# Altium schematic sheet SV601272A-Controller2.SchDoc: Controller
size 431 x 279 mm; Date: Not shown in title block; ApprovedBy: Not shown in title block; CheckedBy: Not shown in title block; Author: Not shown in title block; CompanyName: Not shown in title block; Engineer: Not shown in title block; Organization: Not shown in title block; Address1: Not shown in title block; Address2: Not shown in title block; Address3: Not shown in title block; Address4: Not shown in title block; DocumentNumber: 4; Revision: Use project parameter SCH_Rev; SheetNumber: 4; SheetTotal: 11; PageSetup: Record=PageOptions¦CenterHorizontal=True¦CenterVertical=True¦PrintScale=1.00¦XCorrection=1.00¦YCorrection=1.00¦PrintKind=0¦BorderSize=5000000¦LeftOffset=0¦BottomOffset=0¦Orientation=2¦PaperLength=1000¦PaperWidth=1000¦Scale=100¦PaperSource=15¦PrintQuality=600¦MediaType=1¦DitherType=10¦PaperKind=Letter¦PrintScaleMode=1
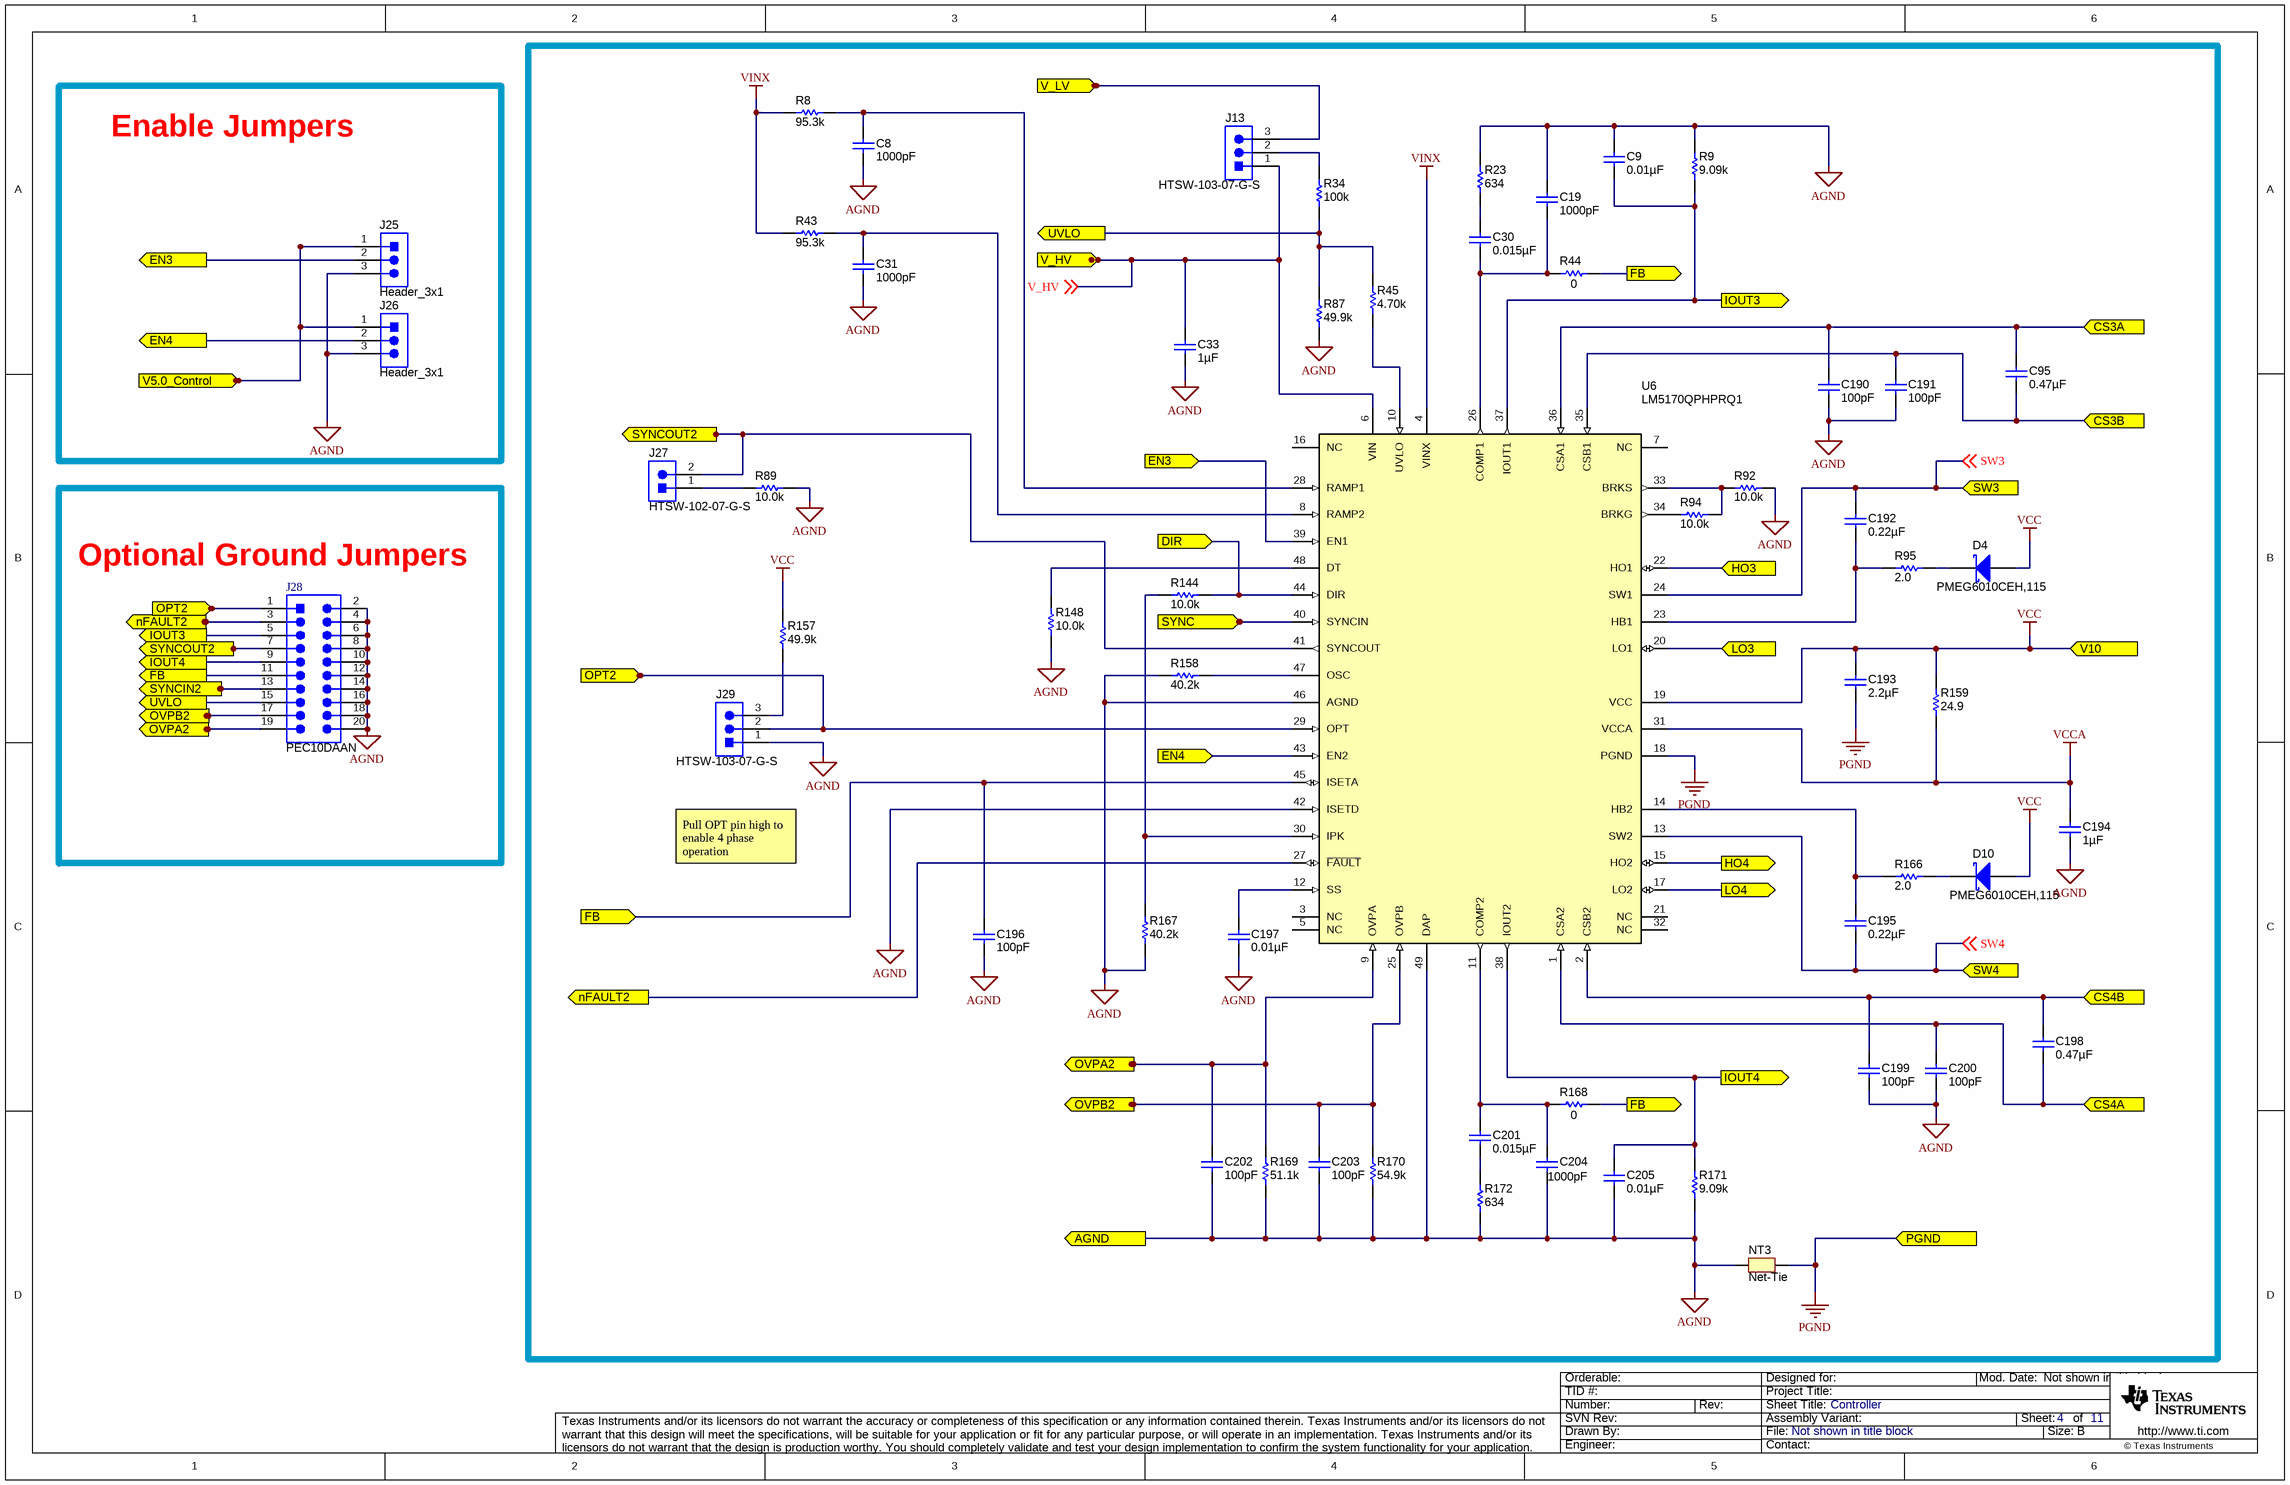
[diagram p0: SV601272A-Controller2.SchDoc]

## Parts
C8  ValueDisplayed: 1000pF  [0603L]  (hidden comment: C1608C0G2A102J080AA)
C9  ValueDisplayed: 0.01µF  [0603L]  (hidden comment: 06031C103KAT2A)
C19  ValueDisplayed: 1000pF  [0603L]  (hidden comment: C1608C0G2A102J080AA)
C30  ValueDisplayed: 0.015µF  [0603L]  (hidden comment: GRM188R71E153KA01D)
C31  ValueDisplayed: 1000pF  [0603L]  (hidden comment: C1608C0G2A102J080AA)
C33  ValueDisplayed: 1µF  [0805_HV]  (hidden comment: C2012X7S2A105K125AB)
C95  ValueDisplayed: 0.47µF  [0603L]  (hidden comment: GRM188R71C474KA88D)
C190  ValueDisplayed: 100pF  [0603L]  (hidden comment: C0603C101J5GACTU)
C191  ValueDisplayed: 100pF  [0603L]  (hidden comment: C0603C101J5GACTU)
C192  ValueDisplayed: 0.22µF  [0603L]  (hidden comment: C1608X7R1H224K080AB)
C193  ValueDisplayed: 2.2µF  [0805_HV]  (hidden comment: C2012X7R1C225K125AB)
C194  ValueDisplayed: 1µF  [0603L]  (hidden comment: GRM188R71E105KA12D)
C195  ValueDisplayed: 0.22µF  [0603L]  (hidden comment: C1608X7R1H224K080AB)
C196  ValueDisplayed: 100pF  [0603L]  (hidden comment: C0603C101J5GACTU)
C197  ValueDisplayed: 0.01µF  [0603L]  (hidden comment: 06031C103KAT2A)
C198  ValueDisplayed: 0.47µF  [0603L]  (hidden comment: GRM188R71C474KA88D)
C199  ValueDisplayed: 100pF  [0603L]  (hidden comment: C0603C101J5GACTU)
C200  ValueDisplayed: 100pF  [0603L]  (hidden comment: C0603C101J5GACTU)
C201  ValueDisplayed: 0.015µF  [0603L]  (hidden comment: GRM188R71E153KA01D)
C202  ValueDisplayed: 100pF  [0603L]  (hidden comment: C0603C101J5GACTU)
C203  ValueDisplayed: 100pF  [0603L]  (hidden comment: C0603C101J5GACTU)
C204  ValueDisplayed: 1000pF  [0603L]  (hidden comment: C1608C0G2A102J080AA)
C205  ValueDisplayed: 0.01µF  [0603L]  (hidden comment: 06031C103KAT2A)
D4  PMEG6010CEH,115  [SOD-123F]
D10  PMEG6010CEH,115  [SOD-123F]
J13  HTSW-103-07-G-S  [Samtec_HTSW-103-07-G-S]
J25  Header_3x1  [Samtec_HTSW-103-07-G-S]
J26  Header_3x1  [Samtec_HTSW-103-07-G-S]
J27  HTSW-102-07-G-S  [Samtec_HTSW-102-07-G-S]
J28  PEC10DAAN  [SULLINS_PEC10DAAN]
J29  HTSW-103-07-G-S  [Samtec_HTSW-103-07-G-S]
NT3  Net-Tie  [Net-Tie_10mil]  (net tie, no BOM)
R8  ValueDisplayed: 95.3k  [0603L]  (hidden comment: CRCW060395K3FKEA)
R9  ValueDisplayed: 9.09k  [0603L]  (hidden comment: CRCW06039K09FKEA)
R23  ValueDisplayed: 634  [0603L]  (hidden comment: CRCW0603634RFKEA)
R34  ValueDisplayed: 100k  [0603]  (hidden comment: CRCW0603100KFKEA)
R43  ValueDisplayed: 95.3k  [0603L]  (hidden comment: CRCW060395K3FKEA)
R44  ValueDisplayed: 0  [0603]  (hidden comment: Resistor)
R45  ValueDisplayed: 4.70k  [0603]  (hidden comment: RC0603FR-074K7L)
R87  ValueDisplayed: 49.9k  [0603]  (hidden comment: ERJ-3EKF4992V)
R89  ValueDisplayed: 10.0k  [0603L]  (hidden comment: CRCW060310K0FKEA)
R92  ValueDisplayed: 10.0k  [0603]  (hidden comment: ERJ-3EKF1002V)
R94  ValueDisplayed: 10.0k  [0603]  (hidden comment: ERJ-3EKF1002V)
R95  ValueDisplayed: 2.0  [0805_HV]  (hidden comment: CRCW08052R00JNEA)
R144  ValueDisplayed: 10.0k  [0603L]  (hidden comment: CRCW060310K0FKEA)
R148  ValueDisplayed: 10.0k  [0603L]  (hidden comment: CRCW060310K0FKEA)
R157  ValueDisplayed: 49.9k  [0603L]  (hidden comment: CRCW060349K9FKEA)
R158  ValueDisplayed: 40.2k  [0603L]  (hidden comment: CRCW060340K2FKEA)
R159  ValueDisplayed: 24.9  [0805L]  (hidden comment: CRCW080524R9FKEA)
R166  ValueDisplayed: 2.0  [0805_HV]  (hidden comment: CRCW08052R00JNEA)
R167  ValueDisplayed: 40.2k  [0603]  (hidden comment: ERJ-3EKF4022V)
R168  ValueDisplayed: 0  [0603]  (hidden comment: Resistor)
R169  ValueDisplayed: 51.1k  [0603L]  (hidden comment: CRCW060351K1FKEA)
R170  ValueDisplayed: 54.9k  [0603L]  (hidden comment: CRCW060354K9FKEA)
R171  ValueDisplayed: 9.09k  [0603L]  (hidden comment: CRCW06039K09FKEA)
R172  ValueDisplayed: 634  [0603L]  (hidden comment: CRCW0603634RFKEA)
U6  LM5170QPHPRQ1  [PHP0048D_L]

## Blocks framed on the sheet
Enable Jumpers: J25 J26
Optional Ground Jumpers: J28

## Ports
AGND, CS3A, CS3B, CS4A, CS4B, DIR, EN3, EN4, FB, HO3, HO4, IOUT3, IOUT4, LO3, LO4, nFAULT2, OPT2, OVPA2, OVPB2, PGND, SW3, SW4, SYNC, SYNCIN2, SYNCOUT2, UVLO, V5.0_Control, V10, V_HV, V_LV

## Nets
AGND: C8.2 C9.1 C19.1 C31.2 C33.2 C190.2 C191.2 C194.2 C196.2 C197.2 C199.2 C200.2 C202.2 C203.2 C204.2 C205.2 J25.3 J26.3 J28.2 J28.4 J28.6 J28.8 J28.10 J28.12 J28.14 J28.16 J28.18 J28.20 J29.1 NT3.1 R9.2 R23.2 R87.1 R89.2 R92.1 R148.1 R158.1 R167.1 R169.1 R170.1 R171.1 R172.1 U6.42(ISETD) U6.46(AGND) U6.49(DAP) ; port AGND
PGND: C193.2 NT3.2 U6.18(PGND) ; port PGND
VCC: C193.1 D4.2(A) D10.2(A) R157.2 R159.2 U6.19(VCC) ; port V10
VCCA: C194.1 R159.1 U6.31(VCCA)
VINX: R8.1 R43.1 U6.4(VINX)
CS3A: C95.1 C190.1 U6.36(CSA1) ; port CS3A
CS3B: C95.2 C191.1 U6.35(CSB1) ; port CS3B
CS4A: C198.2 C200.1 U6.1(CSA2) ; port CS4A
CS4B: C198.1 C199.1 U6.2(CSB2) ; port CS4B
DIR: R144.2 U6.44(DIR) ; port DIR
EN3: J25.2 U6.39(EN1) ; port EN3
EN4: J26.2 U6.43(EN2) ; port EN4
FB: C196.1 J28.11 R44.2 R168.2 U6.45(ISETA) ; port FB
HO3: U6.22(HO1) ; port HO3
HO4: U6.15(HO2) ; port HO4
IOUT3: C9.2 J28.5 R9.1 U6.37(IOUT1) ; port IOUT3
IOUT4: C205.1 J28.9 R171.2 U6.38(IOUT2) ; port IOUT4
LO3: U6.20(LO1) ; port LO3
LO4: U6.17(LO2) ; port LO4
nFAULT2: J28.3 U6.27(~{FAULT}) ; port nFAULT2
OPT2: J28.1 J29.2 U6.29(OPT) ; port OPT2
OVPA2: C202.1 J28.19 R169.2 U6.9(OVPA) ; port OVPA2
OVPB2: C203.1 J28.17 R170.2 U6.25(OVPB) ; port OVPB2
SW3: C192.1 U6.24(SW1) ; off-sheet SW3, port SW3
SW4: C195.2 U6.13(SW2) ; off-sheet SW4, port SW4
SYNC: U6.40(SYNCIN) ; port SYNC
SYNCIN2: J28.13 ; port SYNCIN2
SYNCOUT2: J27.2 J28.7 U6.41(SYNCOUT) ; port SYNCOUT2
UVLO: J28.15 R34.1 R45.2 R87.2 ; port UVLO
V5.0_Control: J25.1 J26.1 ; port V5.0_Control
V_HV: C33.1 J13.1 U6.6(VIN) ; off-sheet V_HV, port V_HV
V_LV: J13.3 ; port V_LV
NetC8_1: C8.1 R8.2 U6.28(RAMP1)
NetC19_2: C19.2 C30.2 R44.1 U6.26(COMP1)
NetC30_1: C30.1 R23.1
NetC31_1: C31.1 R43.2 U6.8(RAMP2)
NetC192_2: C192.2 R95.1 U6.23(HB1)
NetC195_1: C195.1 R166.1 U6.14(HB2)
NetC197_1: C197.1 U6.12(SS)
NetC201_1: C201.1 C204.1 R168.1 U6.11(COMP2)
NetC201_2: C201.2 R172.2
NetD4_1: D4.1(K) R95.2
NetD10_1: D10.1(K) R166.2
NetJ13_2: J13.2 R34.2
NetJ27_1: J27.1 R89.1
NetJ29_3: J29.3 R157.1
NetR45_1: R45.1 U6.10(UVLO)
NetR92_2: R92.2 R94.1 U6.33(BRKS)
NetR94_2: R94.2 U6.34(BRKG)
NetR144_1: R144.1 R167.2 U6.30(IPK)
NetR148_2: R148.2 U6.48(DT)
NetR158_2: R158.2 U6.47(OSC)

Not connected (* = marked no-connect by the designer): U6 3(NC) 5(NC) 7(NC) 16(NC) 21(NC) 32(NC)

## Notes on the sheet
- Pull OPT pin high to enable 4 phase operation

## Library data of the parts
C8 C19 C31 C204 = C1608C0G2A102J080AA: CAP, CERM, 1000 pF, 100 V, +/- 5%, C0G/NP0, 0603; Manufacturer: TDK; Polarized: N; CompType: Capacitor; Value: 1000pF; U/M: EA; Cap_F: 0.000000001; Tolerance_%: 5; ESR_ohm: 0.0589; Value1: 0.0589 ohm; VDC_V: 100; Value2: 100V; TaMin_C: -55; TaMax_C: 125; Cap_Case: 0603; AEC Category: Q200
C9 C197 C205 = 06031C103KAT2A: CAP, CERM, 0.01 µF, 100 V, +/- 10%, X7R, 0603; Manufacturer: AVX; Polarized: N; CompType: Capacitor; Value: 0.01uF; U/M: EA; Cap_F: 0.00000001; Tolerance_%: 10; ESR_ohm: 0.098; Value1: 0.098 ohm; VDC_V: 100; Value2: 100V; TaMin_C: -55; TaMax_C: 125; Cap_Case: 0603
C30 C201 = GRM188R71E153KA01D: CAP, CERM, 0.015 µF, 25 V, +/- 10%, X7R, 0603; Manufacturer: MuRata; Polarized: N; CompType: Capacitor; Value: 0.015uF; U/M: EA; Cap_F: 0.000000015; Tolerance_%: 10; Value1: Unknown; VDC_V: 25; Value2: 25V; TaMin_C: -55; TaMax_C: 125; Cap_Case: 0603
C33 = C2012X7S2A105K125AB: CAP, CERM, 1 µF, 100 V, +/- 10%, X7S, 0805; Manufacturer: TDK; Polarized: N; CompType: Capacitor; Value: 1uF; U/M: EA; Cap_F: 0.000001; Tolerance_%: 10; Value1: Unknown; VDC_V: 100; Value2: 100V; TaMin_C: -55; TaMax_C: 125; Cap_Case: 0805; AEC Category: Q200
C95 C198 = GRM188R71C474KA88D: CAP, CERM, 0.47 µF, 16 V, +/- 10%, X7R, 0603; Manufacturer: MuRata; Polarized: N; CompType: Capacitor; Value: 0.47uF; U/M: EA; Cap_F: 0.00000047; Tolerance_%: 10; Value1: Unknown; VDC_V: 16; Value2: 16V; TaMin_C: -55; TaMax_C: 125; Cap_Case: 0603; AEC Category: Q200
C190 C191 C199 C200 C202 C203 = C0603C101J5GACTU: CAP, CERM, 100 pF, 50 V, +/- 5%, C0G/NP0, 0603; Manufacturer: Kemet; Polarized: N; CompType: Capacitor; Value: 100pF; U/M: EA; Cap_F: 0.0000000001; Tolerance_%: 5; Value1: Unknown; VDC_V: 50; Value2: 50V; TaMin_C: -55; TaMax_C: 125; Cap_Case: 0603; AEC Category: Q200
C192 C195 = C1608X7R1H224K080AB: CAP, CERM, 0.22 µF, 50 V, +/- 10%, X7R, 0603; Manufacturer: TDK; Polarized: N; CompType: Capacitor; Value: 0.22uF; U/M: EA; Cap_F: 0.00000022; Tolerance_%: 10; Value1: Unknown; VDC_V: 50; Value2: 50V; TaMin_C: -55; TaMax_C: 125; Cap_Case: 0603
C193 = C2012X7R1C225K125AB: CAP, CERM, 2.2 µF, 16 V, +/- 10%, X7R, 0805; Manufacturer: TDK; CompType: Capacitor; Value: 2.2uF; U/M: EA; Tolerance_%: 10; VDC_V: 16; Polarized: N; Cap_F: 0.0000022; ESR_ohm: 0.0049; Value1: 0.0049 ohm; Value2: 16V; TaMin_C: -55; TaMax_C: 125; Cap_Case: 0805; AEC Category: Q200
C194 = GRM188R71E105KA12D: CAP, CERM, 1 µF, 25 V, +/- 10%, X7R, 0603; Manufacturer: MuRata; Polarized: N; CompType: Capacitor; Value: 1uF; U/M: EA; Cap_F: 0.000001; Tolerance_%: 10; Value1: Unknown; VDC_V: 25; Value2: 25V; TaMin_C: -55; TaMax_C: 125; Cap_Case: 0603
C196 = C0603C101J5GACTU: CAP, CERM, 100 pF, 50 V, +/- 5%, C0G/NP0, 0603; Manufacturer: Kemet; Polarized: N; CompType: Capacitor; Value: 100pF; U/M: EA; Cap_F: 0.0000000001; Tolerance_%: 5; Value1: Unknown; VDC_V: 50; Value2: 50V; TaMin_C: -55; TaMax_C: 125; Cap_Case: 0603; AEC Category: Q200; SizeArea_mm2: 1.28; SizeAreaWB_mm2: 4.68; SizeX_mm: 1.6; SizeY_mm: 0.8; SizeZ_mm: 1
D4 D10 = PMEG6010CEH,115: Diode, Schottky, 60 V, 1 A, SOD-123F; Manufacturer: NXP Semiconductor; U/M: EA; Vf_V: 0.57; Value: 60V; Value1: 1A; Value2: 0.57V; Io_A: 1; Vr_V: 60; TJmax_C: 150
J13 J29 = HTSW-103-07-G-S: Header, 100mil, 3x1, Gold, TH; Manufacturer: Samtec; SymbolCreator: a0799628; U/M: EA
J25 J26 = CMP-0075484-1: Header, 100mil, 3x1, Gold, TH; PartNumber: HTSW-103-07-G-S; Manufacturer: Samtec; CNHeader: True; CT: False; Green_Lifecycle: Active; Green_REACh: Passed
J27 = HTSW-102-07-G-S: Header, 100mil, 2x1, Gold, TH; Manufacturer: Samtec; SymbolCreator: a0412235; U/M: EA
J28 = CMP-0054623-2: Header, 2.54mm, 10x2, Tin, TH; Manufacturer: Sullins Connector Solutions; Current_A: 3A; Green_Lifecycle: Not Set; Shrouded: N; Gender: Male; Green_REACh: Incomplete; Row_Count: 2; RowSpacing_mm: 2.54; Cert_UL: Y
NT3 = Net-Tie: Single point connection between nets.; SymbolCreator: codlsc
R8 R43 = CRCW060395K3FKEA: RES, 95.3 k, 1%, 0.1 W, 0603; Manufacturer: Vishay-Dale; CompType: Resistor; Value: 95.3k; Res_ohm: 95300; Value_Code: 95k3; Tolerance_%: 1; Power_W: 0.1; Value2: 0.1W; VDC_V: 75; TempCo: 100 ppm/C; EIA_Code: E96; U/M: EA
R9 R171 = CRCW06039K09FKEA: RES, 9.09 k, 1%, 0.1 W, 0603; Manufacturer: Vishay-Dale; CompType: Resistor; Value: 9.09k; Res_ohm: 9090; Value_Code: 9k09; Tolerance_%: 1; Power_W: 0.1; Value2: 0.1W; VDC_V: 75; TempCo: 100 ppm/C; EIA_Code: E96; U/M: EA
R23 R172 = CRCW0603634RFKEA: RES, 634, 1%, 0.1 W, 0603; Manufacturer: Vishay-Dale; CompType: Resistor; Value: 634; Value_Code: 634R; Tolerance_%: 1; Power_W: 0.1; Value2: 0.1W; VDC_V: 75; TempCo: 100 ppm/C; EIA_Code: E96; U/M: EA
R34 = CMP-0021990-4: RES, 100 k, 1%, 0.1 W, AEC-Q200 Grade 0, 0603; Manufacturer: Vishay-Dale; Power_W: 100mW; TempCo: 100 ppm/C; Value: 100k; EIA_Code: E96; SizeX_mm: 1.6; SizeY_mm: 0.8; SizeZ_mm: 1; Value2: 0.1W; SizeArea_mm2: 1.28; CompType: Resistor; AEC Qualified: Y; VDC_V: 75V; AEC Category: Q200; AEC Grade: 0
R44 R168 = CMP-0025874-3: RES, 0, 5%, 0.1 W, 0603; PartNumber: ERJ-3GEY0R00V; Manufacturer: Panasonic; Value: 0; Value_Code: 0000; Power_W: 100mW; Value2: 0.1W; VDC_V: 50V; TempCo: 600 ppm/C; EIA_Code: E24; U/M: EA; AEC Category: Q200; SizeArea_mm2: 1.28; SizeX_mm: 1.6; SizeY_mm: 0.8; SizeZ_mm: 1
R45 = CMP-0023153-3: RES, 4.70 k, 1%, 0.1 W, 0603; Manufacturer: Yageo America; Power_W: 100mW; TempCo: 200 ppm/C; Value_Code: 4k70; U/M: EA; Value: 4.70k; Res_ohm: 4.7k; SizeX_mm: 1.6; SizeY_mm: 0.8; SizeZ_mm: 1; Value2: 0.1W; SizeArea_mm2: 1.28; CompType: Resistor; VDC_V: 150V; AEC Category: Q200
R87 = CMP-0022705-3: RES, 49.9 k, 1%, 0.1 W, AEC-Q200 Grade 0, 0603; Manufacturer: Panasonic; Power_W: 100mW; TempCo: 100 ppm/C; Value_Code: 49k9; U/M: EA; Value: 49.9k; EIA_Code: E96; SizeX_mm: 1.6; SizeY_mm: 0.8; SizeZ_mm: 1; Value2: 0.1W; SizeArea_mm2: 1.28; CompType: Resistor; AEC Qualified: Y; VDC_V: 75V; AEC Grade: 0; AEC Category: Q200
R89 R144 = CRCW060310K0FKEA: RES, 10.0 k, 1%, 0.1 W, 0603; Manufacturer: Vishay-Dale; CompType: Resistor; Value: 10.0k; Res_ohm: 10000; Value_Code: 10k0; Tolerance_%: 1; Power_W: 0.1; Value2: 0.1W; VDC_V: 75; TempCo: 100 ppm/C; EIA_Code: E96; U/M: EA
R92 R94 = CMP-0022684-3: RES, 10.0 k, 1%, 0.1 W, 0603; Manufacturer: Panasonic; Power_W: 100mW; TempCo: 100 ppm/C; Value_Code: 10k0; U/M: EA; Value: 10.0k; EIA_Code: E96; Res_ohm: 10k; SizeX_mm: 1.6; SizeY_mm: 0.8; SizeZ_mm: 1; Value2: 0.1W; SizeArea_mm2: 1.28; CompType: Resistor; VDC_V: 75V; AEC Category: Q200
R95 R166 = CRCW08052R00JNEA: RES, 2.0, 5%, 0.125 W, 0805; Manufacturer: Vishay-Dale; CompType: Resistor; Value: 2.0; Res_ohm: 2; Value_Code: 2R00; Tolerance_%: 5; Power_W: 0.125; Value2: 0.125W; VDC_V: 150; TempCo: 200 ppm/C; EIA_Code: E24; U/M: EA; AEC Category: Q200
R148 = CRCW060310K0FKEA: RES, 10.0 k, 1%, 0.1 W, 0603; Manufacturer: Vishay-Dale; CompType: Resistor; Value: 10.0k; Res_ohm: 10000; Value_Code: 10k0; Tolerance_%: 1; Power_W: 0.1; Value2: 0.1W; VDC_V: 75; TempCo: 100 ppm/C; EIA_Code: E96; U/M: EA; SizeArea_mm2: 1.28; SizeX_mm: 1.6; SizeY_mm: 0.8; AEC Category: Q200
R157 = CRCW060349K9FKEA: RES, 49.9 k, 1%, 0.1 W, 0603; Manufacturer: Vishay-Dale; CompType: Resistor; Value: 49.9k; Res_ohm: 49900; Value_Code: 49k9; Tolerance_%: 1; Power_W: 0.1; Value2: 0.1W; VDC_V: 75; TempCo: 100 ppm/C; EIA_Code: E96; U/M: EA
R158 = CRCW060340K2FKEA: RES, 40.2 k, 1%, 0.1 W, 0603; Manufacturer: Vishay-Dale; CompType: Resistor; Value: 40.2k; Res_ohm: 40200; Value_Code: 40k2; Tolerance_%: 1; Power_W: 0.1; Value2: 0.1W; VDC_V: 75; TempCo: 100 ppm/C; EIA_Code: E96; U/M: EA; SizeArea_mm2: 1.28; SizeX_mm: 1.6; SizeY_mm: 0.8; AEC Category: Q200
R159 = CRCW080524R9FKEA: RES, 24.9, 1%, 0.125 W, 0805; Manufacturer: Vishay-Dale; CompType: Resistor; Value: 24.9; Value_Code: 24R9; Tolerance_%: 1; Power_W: 0.125; Value2: 0.125W; VDC_V: 150; TempCo: 100 ppm/C; EIA_Code: E96; U/M: EA
R167 = CMP-0022700-3: RES, 40.2 k, 1%, 0.1 W, AEC-Q200 Grade 0, 0603; Manufacturer: Panasonic; Power_W: 100mW; TempCo: 100 ppm/C; Value_Code: 40k2; U/M: EA; Value: 40.2k; EIA_Code: E96; SizeX_mm: 1.6; SizeY_mm: 0.8; SizeZ_mm: 1; Value2: 0.1W; SizeArea_mm2: 1.28; CompType: Resistor; AEC Qualified: Y; VDC_V: 75V; AEC Grade: 0; AEC Category: Q200
R169 = CRCW060351K1FKEA: RES, 51.1 k, 1%, 0.1 W, 0603; Manufacturer: Vishay-Dale; CompType: Resistor; Value: 51.1k; Res_ohm: 51100; Value_Code: 51k1; Tolerance_%: 1; Power_W: 0.1; Value2: 0.1W; VDC_V: 75; TempCo: 100 ppm/C; EIA_Code: E96; U/M: EA
R170 = CRCW060354K9FKEA: RES, 54.9 k, 1%, 0.1 W, 0603; Manufacturer: Vishay-Dale; CompType: Resistor; Value: 54.9k; Res_ohm: 54900; Value_Code: 54k9; Tolerance_%: 1; Power_W: 0.1; Value2: 0.1W; VDC_V: 75; TempCo: 100 ppm/C; EIA_Code: E96; U/M: EA
U6 = LM5170QPHPRQ1: Dual Channel 48V-12V Bidirectional Current Controller, PHP0048D; Manufacturer: Texas Instruments; Alternate PartNumber: LM5170QPHPTQ1; SymbolCreator: Altium; CompType: IC; U/M: EA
